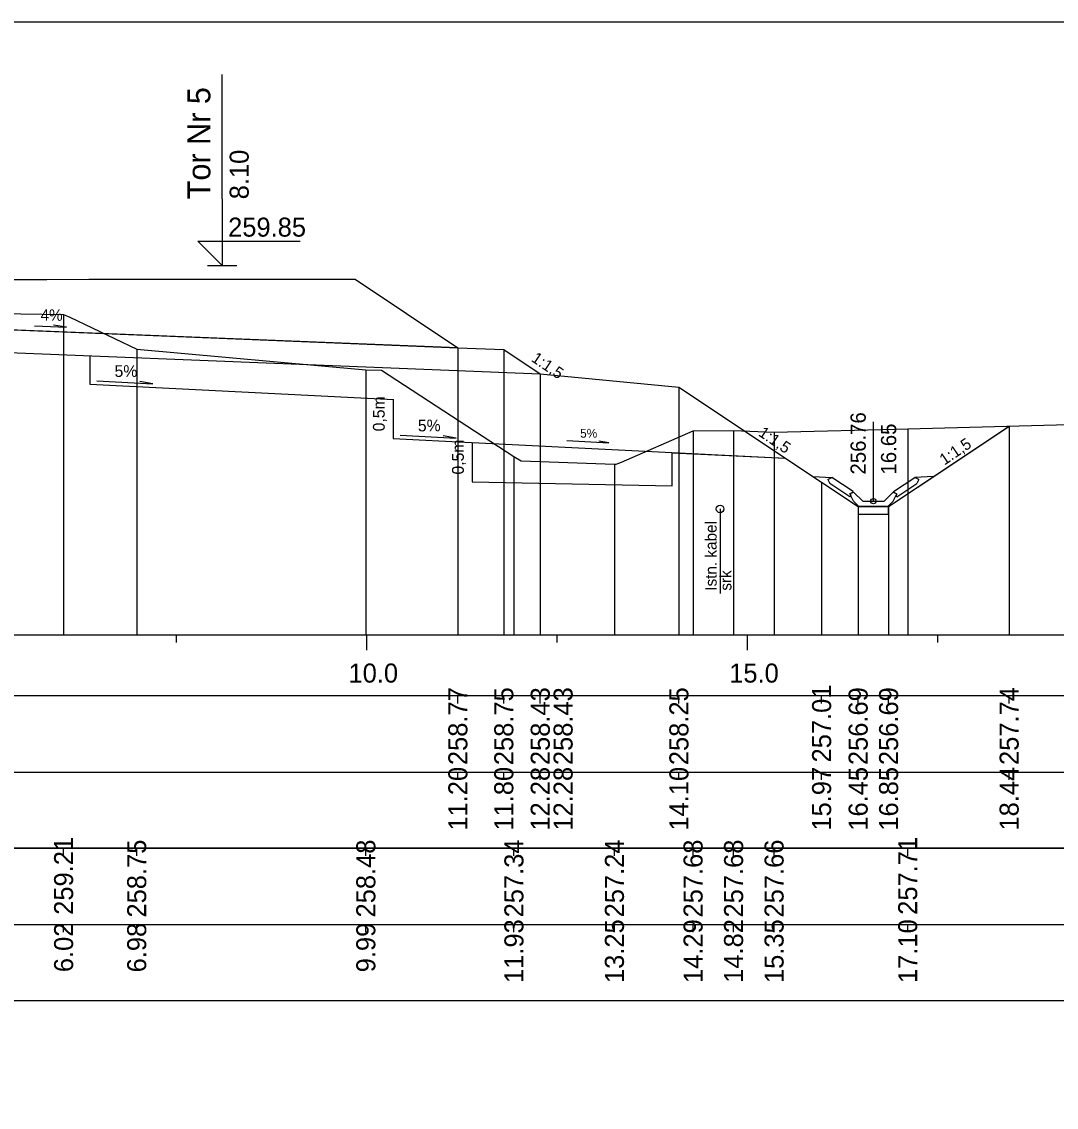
# Model space of a CAD drawing. Extents: x 6516023 to 6560129, y 5513077 to 5529206.
# Drawn here: x 6516574.98 to 6516588.57, y 5514565.91 to 5514580.16 of the extents above; entities that cross this region are included whole.
import ezdxf

# ---------------------------------------------------------------- set-up
doc = ezdxf.new("R2010")
doc.units = 0
for name, color, linetype in [('IR_default', 7, 'Continuous'), ('TOR_PRZEK_P-kable', 7, 'Continuous'), ('TOR_PRZEK_P-komponent', 7, 'Continuous'), ('TOR_PRZEK_P-odwodnienie', 7, 'Continuous'), ('TOR_PRZEK_P-opisy', 7, 'Continuous'), ('TOR_PRZEK_P-schodkowanie+wymiana', 7, 'Continuous'), ('TOR_PRZEK_P-tabelka istniejace', 7, 'Continuous'), ('TOR_PRZEK_P-tabelka projektowane', 7, 'Continuous'), ('TOR_PRZEK_P-teren istniejacy', 7, 'Continuous'), ('TOR_PRZEK_P-tory projektowane', 7, 'Continuous'), ('TOR_PRZEK_P-uklad odniesienia', 7, 'Continuous'), ('TOR_PRZEK_P-warstwa ochronna I', 7, 'Continuous'), ('TOR_PRZEK_P-warstwa ochronna II', 7, 'Continuous'), ('TOR_PS_T-skarpy projektowane', 7, 'Continuous'), ('TOR_RAMKI-ramka+tabelka 1', 7, 'Continuous')]:
    doc.layers.add(name, color=color, linetype=linetype)

msp = doc.modelspace()

# ---------------------------------------------------------------- linework, layer by layer
at = {"layer": 'IR_default'}
msp.add_lwpolyline([(6516573.563, 5514576.773), (6516575.313, 5514576.773), (6516575.863, 5514576.775), (6516579.363, 5514576.775), (6516580.71, 5514575.877), (6516581.313, 5514575.853), (6516581.792, 5514575.534), (6516583.613, 5514575.361), (6516585.487, 5514574.112), (6516585.967, 5514573.792), (6516586.367, 5514573.792), (6516587.117, 5514574.292), (6516587.95, 5514574.848)], dxfattribs=at)
at = {"layer": 'TOR_PRZEK_P-kable'}
msp.add_line((6516584.154, 5514573.761), (6516584.154, 5514572.651), dxfattribs=at)
msp.add_circle((6516584.154, 5514573.761), 0.05, dxfattribs=at)
at = {"layer": 'TOR_PRZEK_P-komponent'}
msp.add_lwpolyline([(6516563.663, 5514576.774), (6516565.413, 5514576.774), (6516564.159, 5514576.774), (6516567.163, 5514576.774), (6516567.763, 5514576.774), (6516569.513, 5514576.774), (6516571.263, 5514576.774), (6516571.813, 5514576.773), (6516573.563, 5514576.773), (6516575.313, 5514576.773), (6516575.863, 5514576.775), (6516579.363, 5514576.775), (6516580.71, 5514575.877), (6516571.538, 5514576.244), (6516562.314, 5514575.875)], close=True, dxfattribs=at)
at = {"layer": 'TOR_PRZEK_P-odwodnienie'}
for p, q in [((6516586.167, 5514573.862), (6516586.167, 5514574.906)), ((6516585.902, 5514573.988), (6516585.622, 5514574.175)), ((6516586.431, 5514573.988), (6516586.712, 5514574.175)), ((6516585.858, 5514573.921), (6516585.596, 5514574.095)), ((6516586.476, 5514573.921), (6516586.737, 5514574.095)), ((6516585.869, 5514573.938), (6516585.858, 5514573.921)), ((6516585.859, 5514573.957), (6516585.907, 5514573.981)), ((6516585.902, 5514573.988), (6516585.894, 5514573.975)), ((6516586.027, 5514573.862), (6516585.907, 5514573.981)), ((6516586.307, 5514573.862), (6516586.427, 5514573.981)), ((6516586.427, 5514573.981), (6516586.474, 5514573.957)), ((6516586.431, 5514573.988), (6516586.439, 5514573.975)), ((6516586.464, 5514573.938), (6516586.476, 5514573.921)), ((6516585.977, 5514573.792), (6516586.357, 5514573.792)), ((6516586.027, 5514573.862), (6516586.307, 5514573.862))]:
    msp.add_line(p, q, dxfattribs=at)
for points in [[(6516585.375, 5514574.186), (6516585.622, 5514574.175)], [(6516585.571, 5514574.148), (6516585.622, 5514574.175)], [(6516586.958, 5514574.186), (6516586.712, 5514574.175)], [(6516586.762, 5514574.148), (6516586.712, 5514574.175)], [(6516585.571, 5514574.148), (6516585.596, 5514574.095)], [(6516586.762, 5514574.148), (6516586.737, 5514574.095)], [(6516585.894, 5514573.975), (6516585.858, 5514573.957)], [(6516585.858, 5514573.957), (6516585.869, 5514573.938)], [(6516585.907, 5514573.862), (6516585.859, 5514573.957)], [(6516586.427, 5514573.862), (6516586.474, 5514573.957)], [(6516586.439, 5514573.975), (6516586.475, 5514573.957)], [(6516586.475, 5514573.957), (6516586.464, 5514573.938)], [(6516585.977, 5514573.792), (6516585.907, 5514573.862)], [(6516585.967, 5514573.792), (6516585.966, 5514573.792), (6516585.967, 5514573.792), (6516585.966, 5514573.791), (6516585.967, 5514573.792), (6516585.967, 5514573.791), (6516585.967, 5514573.792), (6516585.967, 5514573.792)], [(6516586.367, 5514573.792), (6516585.967, 5514573.792), (6516585.967, 5514573.692), (6516586.367, 5514573.692), (6516586.367, 5514573.792)], [(6516586.357, 5514573.792), (6516586.427, 5514573.862)], [(6516586.367, 5514573.792), (6516586.366, 5514573.792), (6516586.367, 5514573.792), (6516586.366, 5514573.791), (6516586.367, 5514573.792), (6516586.367, 5514573.791), (6516586.367, 5514573.792), (6516586.367, 5514573.792)]]:
    msp.add_lwpolyline(points, dxfattribs=at)
msp.add_circle((6516586.167, 5514573.862), 0.035, dxfattribs=at)
at = {"layer": 'TOR_PRZEK_P-opisy'}
msp.add_lwpolyline([(6516575.15, 5514576.165), (6516575.568, 5514576.146), (6516575.4, 5514576.175)], dxfattribs=at)
at = {"layer": 'TOR_PRZEK_P-schodkowanie+wymiana'}
for p, q in [((6516575.876, 5514575.77), (6516575.876, 5514575.397)), ((6516575.876, 5514575.397), (6516579.869, 5514575.197)), ((6516579.86, 5514575.198), (6516579.86, 5514574.683)), ((6516579.86, 5514574.683), (6516580.89, 5514574.631)), ((6516580.899, 5514574.631), (6516580.899, 5514574.116)), ((6516580.899, 5514574.631), (6516585.003, 5514574.426))]:
    msp.add_line(p, q, dxfattribs=at)
msp.add_lwpolyline([(6516580.899, 5514574.116), (6516583.525, 5514574.066), (6516583.525, 5514574.499), (6516585.017, 5514574.425)], dxfattribs=at)
at = {"layer": 'TOR_PRZEK_P-tabelka istniejace'}
for p, q in [((6516575.532, 5514569.206), (6516575.532, 5514569.306)), ((6516576.492, 5514569.206), (6516576.492, 5514569.306)), ((6516579.501, 5514569.206), (6516579.501, 5514569.306)), ((6516581.446, 5514569.206), (6516581.446, 5514569.306)), ((6516582.766, 5514569.206), (6516582.766, 5514569.306)), ((6516583.799, 5514569.206), (6516583.799, 5514569.306)), ((6516584.331, 5514569.206), (6516584.331, 5514569.306)), ((6516584.863, 5514569.206), (6516584.863, 5514569.306)), ((6516586.618, 5514569.206), (6516586.618, 5514569.306)), ((6516528.663, 5514568.306), (6516607.463, 5514568.306)), ((6516575.532, 5514568.206), (6516575.532, 5514568.306)), ((6516576.492, 5514568.206), (6516576.492, 5514568.306)), ((6516579.501, 5514568.206), (6516579.501, 5514568.306)), ((6516581.446, 5514568.206), (6516581.446, 5514568.306)), ((6516582.766, 5514568.206), (6516582.766, 5514568.306)), ((6516583.799, 5514568.206), (6516583.799, 5514568.306)), ((6516584.331, 5514568.206), (6516584.331, 5514568.306)), ((6516584.863, 5514568.206), (6516584.863, 5514568.306)), ((6516586.618, 5514568.206), (6516586.618, 5514568.306))]:
    msp.add_line(p, q, dxfattribs=at)
for points in [[(6516575.532, 5514576.315), (6516575.532, 5514572.306), (6516575.532, 5514572.176), (6516575.532, 5514572.106)], [(6516576.492, 5514575.859), (6516576.492, 5514572.306), (6516576.492, 5514572.176), (6516576.492, 5514572.106)], [(6516579.501, 5514575.586), (6516579.501, 5514572.306), (6516579.501, 5514572.176), (6516579.501, 5514572.106)], [(6516583.799, 5514574.784), (6516583.799, 5514572.306), (6516583.799, 5514572.176), (6516583.799, 5514572.106)], [(6516584.331, 5514574.789), (6516584.331, 5514572.306), (6516584.331, 5514572.176), (6516584.331, 5514572.106)], [(6516584.863, 5514574.77), (6516584.863, 5514572.306), (6516584.863, 5514572.176), (6516584.863, 5514572.106)], [(6516586.618, 5514574.812), (6516586.618, 5514572.306), (6516586.618, 5514572.176), (6516586.618, 5514572.106)], [(6516581.446, 5514574.451), (6516581.446, 5514572.306), (6516581.446, 5514572.176), (6516581.446, 5514572.106)], [(6516582.766, 5514574.349), (6516582.766, 5514572.306), (6516582.766, 5514572.176), (6516582.766, 5514572.106)]]:
    msp.add_lwpolyline(points, dxfattribs=at)
msp.add_lwpolyline([(6516528.663, 5514569.306), (6516528.663, 5514567.306), (6516607.463, 5514567.306), (6516607.463, 5514569.306)], close=True, dxfattribs=at)
at = {"layer": 'TOR_PRZEK_P-tabelka projektowane'}
for p, q in [((6516580.71, 5514571.206), (6516580.71, 5514571.306)), ((6516581.313, 5514571.206), (6516581.313, 5514571.306)), ((6516581.792, 5514571.206), (6516581.792, 5514571.306)), ((6516583.613, 5514571.206), (6516583.613, 5514571.306)), ((6516585.487, 5514571.206), (6516585.487, 5514571.306)), ((6516585.967, 5514571.206), (6516585.967, 5514571.306)), ((6516586.367, 5514571.206), (6516586.367, 5514571.306)), ((6516587.95, 5514571.206), (6516587.95, 5514571.306)), ((6516528.663, 5514570.306), (6516607.463, 5514570.306)), ((6516580.71, 5514570.206), (6516580.71, 5514570.306)), ((6516581.313, 5514570.206), (6516581.313, 5514570.306)), ((6516581.792, 5514570.206), (6516581.792, 5514570.306)), ((6516583.613, 5514570.206), (6516583.613, 5514570.306)), ((6516585.487, 5514570.206), (6516585.487, 5514570.306)), ((6516585.967, 5514570.206), (6516585.967, 5514570.306)), ((6516586.367, 5514570.206), (6516586.367, 5514570.306)), ((6516587.95, 5514570.206), (6516587.95, 5514570.306))]:
    msp.add_line(p, q, dxfattribs=at)
for points in [[(6516580.71, 5514575.877), (6516580.71, 5514572.306), (6516580.71, 5514572.176), (6516580.71, 5514572.106)], [(6516581.313, 5514575.853), (6516581.313, 5514572.306), (6516581.313, 5514572.176), (6516581.313, 5514572.106)], [(6516581.792, 5514575.534), (6516581.792, 5514572.306), (6516581.792, 5514572.176), (6516581.792, 5514572.106)], [(6516583.613, 5514575.361), (6516583.613, 5514572.306), (6516583.613, 5514572.176), (6516583.613, 5514572.106)], [(6516587.95, 5514574.848), (6516587.95, 5514572.306), (6516587.95, 5514572.176), (6516587.95, 5514572.106)], [(6516585.487, 5514574.112), (6516585.487, 5514572.306), (6516585.487, 5514572.176), (6516585.487, 5514572.106)], [(6516585.967, 5514573.792), (6516585.967, 5514572.306), (6516585.967, 5514572.176), (6516585.967, 5514572.106)], [(6516586.367, 5514573.792), (6516586.367, 5514572.306), (6516586.367, 5514572.176), (6516586.367, 5514572.106)]]:
    msp.add_lwpolyline(points, dxfattribs=at)
msp.add_lwpolyline([(6516528.663, 5514571.306), (6516528.663, 5514569.306), (6516607.463, 5514569.306), (6516607.463, 5514571.306)], close=True, dxfattribs=at)
at = {"layer": 'TOR_PRZEK_P-teren istniejacy'}
msp.add_lwpolyline([(6516559.125, 5514576.301), (6516562.09, 5514576.283), (6516562.939, 5514575.919), (6516562.98, 5514575.892), (6516563.518, 5514575.874), (6516563.55, 5514575.873), (6516563.62, 5514575.914), (6516564.548, 5514576.504), (6516574.684, 5514576.325), (6516575.532, 5514576.315), (6516575.614, 5514576.279), (6516576.492, 5514575.859), (6516579.501, 5514575.586), (6516579.705, 5514575.58), (6516581.446, 5514574.451), (6516581.54, 5514574.394), (6516582.766, 5514574.349), (6516582.791, 5514574.348), (6516582.858, 5514574.375), (6516583.799, 5514574.784), (6516584.331, 5514574.789), (6516584.863, 5514574.77), (6516586.618, 5514574.812), (6516591.657, 5514574.949)], dxfattribs=at)
at = {"layer": 'TOR_PRZEK_P-tory projektowane'}
for p, q in [((6516577.613, 5514577.832), (6516577.613, 5514579.464)), ((6516577.613, 5514577.832), (6516577.613, 5514576.955)), ((6516577.613, 5514576.955), (6516577.294, 5514577.274)), ((6516577.294, 5514577.274), (6516578.638, 5514577.274)), ((6516577.421, 5514576.955), (6516577.805, 5514576.955))]:
    msp.add_line(p, q, dxfattribs=at)
at = {"layer": 'TOR_PRZEK_P-uklad odniesienia'}
for p, q in [((6516532.463, 5514572.106), (6516607.463, 5514572.106)), ((6516577.013, 5514572.006), (6516577.013, 5514572.106)), ((6516579.513, 5514571.906), (6516579.513, 5514572.106)), ((6516582.013, 5514572.006), (6516582.013, 5514572.106)), ((6516584.513, 5514571.906), (6516584.513, 5514572.106)), ((6516587.013, 5514572.006), (6516587.013, 5514572.106))]:
    msp.add_line(p, q, dxfattribs=at)
at = {"layer": 'TOR_PRZEK_P-warstwa ochronna I'}
msp.add_lwpolyline([(6516561.234, 5514575.532), (6516571.538, 5514575.944), (6516581.792, 5514575.534)], dxfattribs=at)
at = {"layer": 'TOR_PRZEK_P-warstwa ochronna II'}
msp.add_lwpolyline([(6516549.367, 5514575.36), (6516552.573, 5514573.492), (6516553.323, 5514573.492), (6516553.728, 5514573.762), (6516555.913, 5514575.219), (6516561.234, 5514575.532), (6516561.713, 5514575.851), (6516562.314, 5514575.875), (6516570.263, 5514576.194), (6516571.538, 5514576.244), (6516572.813, 5514576.193), (6516580.71, 5514575.877), (6516581.313, 5514575.853), (6516581.792, 5514575.534), (6516583.613, 5514575.361), (6516585.487, 5514574.112), (6516585.967, 5514573.792), (6516586.367, 5514573.792), (6516587.95, 5514574.848)], dxfattribs=at)
at = {"layer": 'TOR_PS_T-skarpy projektowane'}
for points in [[(6516575.969, 5514575.441), (6516576.704, 5514575.402), (6516576.531, 5514575.433)], [(6516579.953, 5514574.727), (6516580.688, 5514574.688), (6516580.516, 5514574.718)], [(6516582.142, 5514574.657), (6516582.693, 5514574.627), (6516582.563, 5514574.65)]]:
    msp.add_lwpolyline(points, dxfattribs=at)
at = {"layer": 'TOR_RAMKI-ramka+tabelka 1'}
msp.add_lwpolyline([(6516362.013, 5514580.156), (6516609.513, 5514580.156), (6516609.513, 5514551.656), (6516362.013, 5514551.656)], close=True, dxfattribs=at)

# ---------------------------------------------------------------- texts
at = {"layer": 'TOR_PRZEK_P-kable'}
for s, height, p in [('Istn. kabel', 0.14999, (6516584.109, 5514572.687)), ('srk', 0.15, (6516584.303, 5514572.688))]:
    msp.add_text(s, height=height, rotation=90.0511, dxfattribs=at).set_placement(p)
at = {"layer": 'TOR_PRZEK_P-odwodnienie'}
for s, p in [('256.76', (6516586.067, 5514574.212)), ('16.65', (6516586.467, 5514574.212))]:
    msp.add_text(s, height=0.2, rotation=90, dxfattribs=at).set_placement(p)
at = {"layer": 'TOR_PRZEK_P-opisy'}
for s, rotation, p in [('4%', 359.8485, (6516575.229, 5514576.231)), ('1:1,5', 325.9299, (6516581.664, 5514575.707)), ('1:1,5', 325.9299, (6516584.646, 5514574.73)), ('1:1,5', 34.0701, (6516587.1, 5514574.329))]:
    msp.add_text(s, height=0.15, rotation=rotation, dxfattribs=at).set_placement(p)
at = {"layer": 'TOR_PRZEK_P-schodkowanie+wymiana'}
for p in [(6516579.749, 5514574.779), (6516580.788, 5514574.212)]:
    msp.add_text('0,5m', height=0.1545, rotation=90, dxfattribs=at).set_placement(p)
at = {"layer": 'TOR_PRZEK_P-tabelka istniejace'}
for s, p in [('259.21', (6516575.657, 5514568.433)), ('258.75', (6516576.617, 5514568.397)), ('258.48', (6516579.626, 5514568.398)), ('257.34', (6516581.571, 5514568.399)), ('257.24', (6516582.891, 5514568.399)), ('257.68', (6516583.924, 5514568.398)), ('257.68', (6516584.456, 5514568.398)), ('257.66', (6516584.988, 5514568.398)), ('257.71', (6516586.743, 5514568.433)), ('6.02', (6516575.657, 5514567.68)), ('6.98', (6516576.617, 5514567.677)), ('9.99', (6516579.626, 5514567.678)), ('11.93', (6516581.571, 5514567.538)), ('13.25', (6516582.891, 5514567.537)), ('14.29', (6516583.924, 5514567.538)), ('14.82', (6516584.456, 5514567.54)), ('15.35', (6516584.988, 5514567.537)), ('17.10', (6516586.743, 5514567.538))]:
    msp.add_text(s, height=0.25, rotation=90, dxfattribs=at).set_placement(p)
at = {"layer": 'TOR_PRZEK_P-tabelka projektowane'}
for s, p in [('258.77', (6516580.835, 5514570.398)), ('258.75', (6516581.438, 5514570.397)), ('258.43', (6516581.917, 5514570.398)), ('258.43', (6516582.217, 5514570.398)), ('258.25', (6516583.738, 5514570.397)), ('257.01', (6516585.612, 5514570.433)), ('256.69', (6516586.092, 5514570.398)), ('256.69', (6516586.492, 5514570.398)), ('257.74', (6516588.075, 5514570.399)), ('11.20', (6516580.835, 5514569.538)), ('11.80', (6516581.438, 5514569.538)), ('12.28', (6516581.917, 5514569.538)), ('12.28', (6516582.217, 5514569.538)), ('14.10', (6516583.738, 5514569.538)), ('15.97', (6516585.612, 5514569.538)), ('16.45', (6516586.092, 5514569.537)), ('16.85', (6516586.492, 5514569.537)), ('18.44', (6516588.075, 5514569.539))]:
    msp.add_text(s, height=0.25, rotation=90, dxfattribs=at).set_placement(p)
at = {"layer": 'TOR_PRZEK_P-tory projektowane'}
for s, height, p in [('Tor Nr 5', 0.3, (6516577.459, 5514577.826)), ('8.10', 0.25, (6516577.963, 5514577.825))]:
    msp.add_text(s, height=height, rotation=90, dxfattribs=at).set_placement(p)
msp.add_text('259.85', height=0.25, dxfattribs=at).set_placement((6516577.693, 5514577.335))
at = {"layer": 'TOR_PRZEK_P-uklad odniesienia'}
for s, p in [('10.0', (6516579.274, 5514571.481)), ('15.0', (6516584.274, 5514571.481))]:
    msp.add_text(s, height=0.25, dxfattribs=at).set_placement(p)
at = {"layer": 'TOR_PS_T-skarpy projektowane'}
for height, p in [(0.1545, (6516576.201, 5514575.493)), (0.1545, (6516580.185, 5514574.779)), (0.1159, (6516582.316, 5514574.696))]:
    msp.add_text('5%', height=height, dxfattribs=at).set_placement(p)

doc.saveas('drawing.dxf')
